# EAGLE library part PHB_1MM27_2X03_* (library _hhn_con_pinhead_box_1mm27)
Pin Header Box-Type, 1.27mm/0.5"/50mil Pitch, 2x03 Circuits Note: see library description for an important note about THT-version
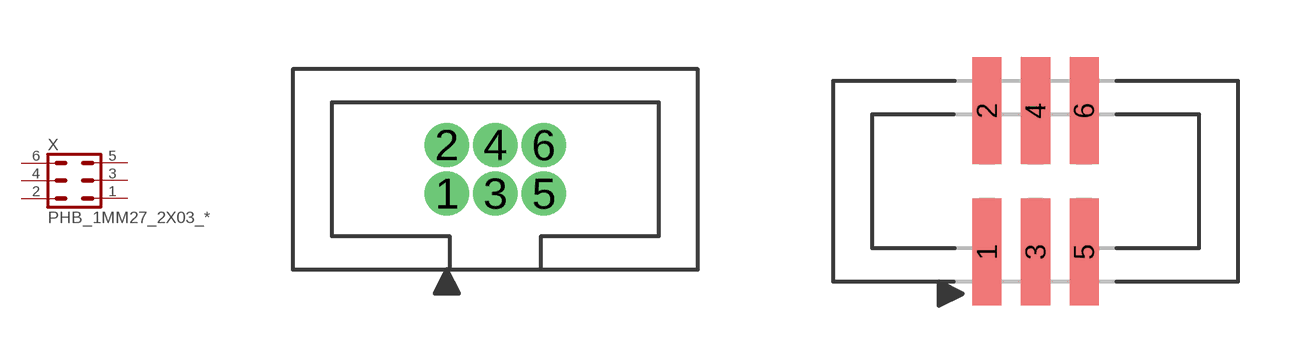
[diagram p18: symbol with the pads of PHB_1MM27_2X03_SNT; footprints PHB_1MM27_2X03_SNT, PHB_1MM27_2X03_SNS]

Designator prefix X

## PHB_1MM27_2X03_SNT  [PHB_1MM27_2X03_SNT]
1  1  pas
2  2  pas
3  3  pas
4  4  pas
5  5  pas
6  6  pas

## PHB_1MM27_2X03_SNS  [PHB_1MM27_2X03_SNS]
Pads as for PHB_1MM27_2X03_SNT

## Footprint PHB_1MM27_2X03_SNT (pad centres in mm)
Pin Header Box-Type, 1.27mm Pitch, 2x03 circuits, Straight, No Locking, THT Important Note: Diameter in this lbr is set to a specific value (NOT 'auto' = 0), this is ignored by actual eagle versions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
drill 0.65 pad 1 round: 1 -1.27,-0.635; 2 -1.27,0.635; 3 0,-0.635; 4 0,0.635; 5 1.27,-0.635; 6 1.27,0.635

## Footprint PHB_1MM27_2X03_SNS (pad centres in mm)
Pin Header Box-Type, 1.27mm Pitch, 2x03 circuits, Straight, No Locking, SMT
smd 0.76 x 2.8: 1 -1.27,-1.85; 2 -1.27,1.85; 3 0,-1.85; 4 0,1.85; 5 1.27,-1.85; 6 1.27,1.85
